RoboDK station: New Station (1).rdk

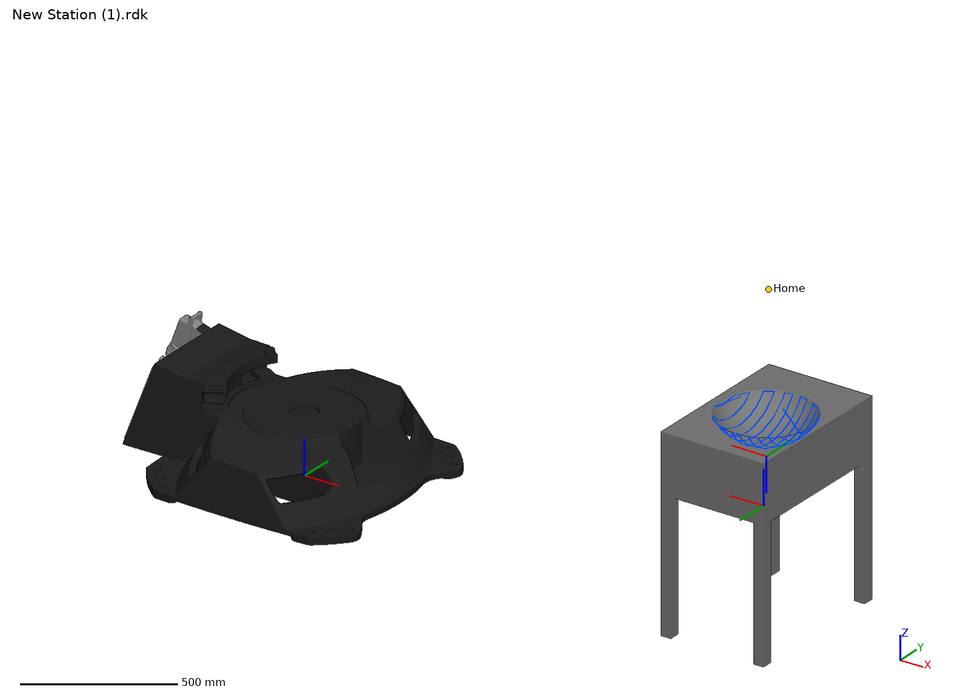
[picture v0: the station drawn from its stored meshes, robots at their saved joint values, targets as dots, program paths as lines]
Station New Station (1) (saved by RoboDK 5.5.4). Poses are relative to the parent item; angles as X-Y-Z fixed-axis rotations.
  - frame KUKA KR 90 R2700 pro Base at (0, 0, 0) mm
    - robot KUKA KR 90 R2700 pro: 6 axes, payload 90 kg, reach 2700 mm, repeatability 0.06 mm, weight 1058 kg
        joint limits [-185, -140, -120, -350, -125, -350] to [185, -5, 155, 350, 125, 350]; home [0, -90, 90, 0, 0, 0]; saved at [0, -80.946, 98.354, 0, 43.832, 0]
      - tool Nastroj, TCP at (0, 0, 70) mm, size 183.8 x 183.3 x 59.7 mm, geometry from Nastroj.stp
    - target Home (joint target) at (1800.87, 0, 1162.68) mm, rotated rx 180 ry 28.76 rz 180 deg; joints [0, -80.946, 98.354, 0, 43.832, 0] of KUKA KR 90 R2700 pro
  - frame Stul Frame at (1790, 0, 570) mm, rotated rx 180 ry 0 rz -180 deg
    - object Stul at (0, 0, 0) mm, rotated rx 0 ry 0 rz 90 deg, size 600 x 400 x 570 mm, geometry from Stul.stp
    - frame Frame Dilek_Test at (-200, -300, 0) mm, rotated rx 180 ry 0 rz 0 deg
      - object Dil23 at (0, 0, 0) mm, size 400 x 600 x 150 mm, geometry from Dil23.step
      - object Polish Path 1 at (0, 0, 0) mm, geometry from tyle
      - object Sphere at (200, -300, 250) mm, size 399.9 x 399.9 x 400 mm, geometry from Sphere.stp
  - program GoHome (3 instructions, listed below)
  - program Main (5 instructions, listed below)
  - machining project Polish Path 1 Settings: rotZ(0 | rotX(0)*rotY(0 | rotz(0) | onStart | onPathStart | onApproach | onPoint | onRetract | onFinish | SetRPM(%1) | SetTool(%1) | Extruder(%1) | default | default | OutOnMov(%1) | OutOffMov(%1) | onPathFinis | M_RunCode(%1
  - program Polish (260 instructions, listed below)
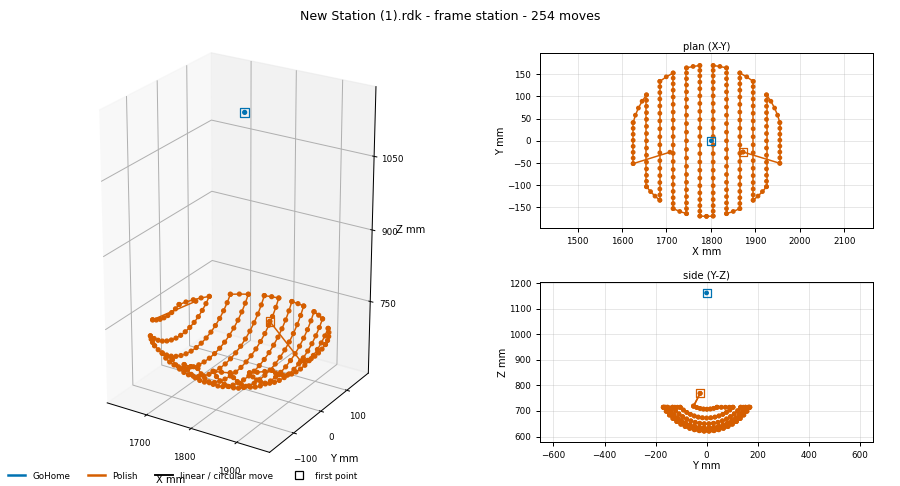
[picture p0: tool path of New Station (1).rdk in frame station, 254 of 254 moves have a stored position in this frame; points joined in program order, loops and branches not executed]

--- program GoHome (robot KUKA KR 90 R2700 pro) ---
  Set Ref.: KUKA KR 90 R2700 pro Base
  Set Tool: Nastroj
  MoveJ (Home)

--- program Main (robot KUKA KR 90 R2700 pro) ---
  Set Ref.: Stul Frame
  Set Tool: Nastroj
  Call GoHome
  Call Polish
  Call GoHome

--- program Polish (robot KUKA KR 90 R2700 pro) ---
  Smooth(1)
  Set speed (1000.0 mm/s)
  Set Ref.: Frame Dilek_Test
  Set Tool: Nastroj
  Show Nastroj
  MoveJ 1 to (117.8, -274.8, 198.93) mm, rotated rx -137.84 ry 47.58 rz 33.76 deg; joints [-1.651, -68.453, 110.438, 122.535, 19.225, -102.13]
  MoveL 2 to (117.8, -274.8, 198.93) mm, rotated rx -137.84 ry 47.58 rz 33.76 deg; joints [-1.651, -68.453, 110.438, 122.535, 19.225, -102.13]
  MoveL 3 to (35, -249.41, 148.93) mm, rotated rx -137.84 ry 47.58 rz 33.76 deg; joints [-0.725, -63.471, 106.074, 125.742, 19.006, -104.865]
  MoveL 4 to (35, -249.41, 148.93) mm, rotated rx -137.84 ry 47.58 rz 33.76 deg; joints [-0.725, -63.471, 106.074, 125.742, 19.006, -104.865]
  Set speed (50.0 mm/s)
  MoveL 5 to (35, -261.79, 143.63) mm, rotated rx -143.95 ry 51.8 rz 29.77 deg; joints [-0.584, -63.444, 106.387, 135.478, 16.911, -118.801]
  MoveL 6 to (35, -274.71, 139.84) mm, rotated rx -153.09 ry 55.89 rz 22.79 deg; joints [-0.405, -63.435, 106.629, 148.134, 15.066, -136.573]
  MoveL 7 to (35, -288, 137.61) mm, rotated rx -166 ry 58.98 rz 12.06 deg; joints [-0.198, -63.435, 106.779, 163.971, 13.789, -158.315]
  MoveL 8 to (35, -301.45, 136.98) mm, rotated rx 178.26 ry 59.98 rz -1.51 deg; joints [0.024, -63.435, 106.823, 181.974, 13.394, -182.664]
  MoveL 9 to (35, -314.88, 137.96) mm, rotated rx 162.91 ry 58.46 rz -14.69 deg; joints [0.244, -63.435, 106.756, 199.683, 13.999, -206.663]
  MoveL 10 to (35, -328.1, 140.52) mm, rotated rx 150.82 ry 55.06 rz -24.6 deg; joints [0.446, -63.436, 106.584, 214.864, 15.427, -227.6]
  MoveL 11 to (35, -340.93, 144.64) mm, rotated rx 142.41 ry 50.88 rz -30.84 deg; joints [0.618, -63.448, 106.325, 226.844, 17.35, -244.503]
  MoveL 12 to (35, -340.93, 144.64) mm, rotated rx 142.41 ry 50.88 rz -30.84 deg; joints [0.618, -63.448, 106.325, 226.844, 17.35, -244.503]
  MoveL 13 to (40.06, -357.6, 144.64) mm, rotated rx 134.65 ry 44.65 rz -35.43 deg; joints [0.868, -63.359, 106.183, 238.953, 20.907, -262.28]
  MoveL 14 to (46.79, -373.67, 144.64) mm, rotated rx 129.79 ry 38.63 rz -36.85 deg; joints [1.108, -63.241, 105.994, 248.006, 24.894, -275.71]
  MoveL 15 to (55.13, -388.96, 144.64) mm, rotated rx 126.67 ry 33.15 rz -36.29 deg; joints [1.335, -63.095, 105.759, 255.096, 29.12, -285.986]
  MoveL 16 to (65, -403.32, 144.64) mm, rotated rx 124.59 ry 28.27 rz -34.48 deg; joints [1.547, -62.923, 105.482, 260.918, 33.479, -293.97]
  MoveL 17 to (65, -403.32, 144.64) mm, rotated rx 124.59 ry 28.27 rz -34.48 deg; joints [1.547, -62.923, 105.482, 260.918, 33.479, -293.97]
  MoveL 18 to (65, -391.04, 133.86) mm, rotated rx 125.71 ry 31.05 rz -35.67 deg; joints [1.564, -62.846, 106.082, 256.775, 31.153, -288.422]
  MoveL 19 to (65, -377.64, 124.51) mm, rotated rx 127.42 ry 34.63 rz -36.6 deg; joints [1.52, -62.84, 106.709, 251.428, 28.444, -281.096]
  MoveL 20 to (65, -363.28, 116.69) mm, rotated rx 130.17 ry 39.18 rz -36.81 deg; joints [1.396, -62.894, 107.336, 244.35, 25.394, -271.155]
  MoveL 21 to (65, -348.15, 110.51) mm, rotated rx 134.83 ry 44.83 rz -35.34 deg; joints [1.177, -62.988, 107.92, 234.707, 22.143, -257.358]
  MoveL 22 to (65, -332.43, 106.05) mm, rotated rx 143.12 ry 51.31 rz -30.35 deg; joints [0.858, -63.092, 108.403, 221.278, 19.01, -238.058]
  MoveL 23 to (65, -316.32, 103.34) mm, rotated rx 157.85 ry 57.33 rz -18.91 deg; joints [0.454, -63.173, 108.726, 202.827, 16.583, -211.871]
  MoveL 24 to (65, -300, 102.44) mm, rotated rx -180 ry 60 rz 0 deg; joints [0, -63.204, 108.84, 180, 15.637, -180]
  MoveL 25 to (65, -283.68, 103.34) mm, rotated rx -157.85 ry 57.33 rz 18.91 deg; joints [-0.454, -63.173, 108.726, 157.173, 16.583, -148.129]
  MoveL 26 to (65, -267.57, 106.05) mm, rotated rx -143.12 ry 51.31 rz 30.35 deg; joints [-0.858, -63.092, 108.403, 138.722, 19.01, -121.942]
  MoveL 27 to (65, -251.85, 110.51) mm, rotated rx -134.83 ry 44.83 rz 35.34 deg; joints [-1.177, -62.988, 107.92, 125.293, 22.143, -102.642]
  MoveL 28 to (65, -236.72, 116.69) mm, rotated rx -130.17 ry 39.18 rz 36.81 deg; joints [-1.396, -62.894, 107.336, 115.65, 25.394, -88.845]
  MoveL 29 to (65, -222.36, 124.51) mm, rotated rx -127.42 ry 34.63 rz 36.6 deg; joints [-1.52, -62.84, 106.709, 108.572, 28.444, -78.904]
  MoveL 30 to (65, -208.96, 133.86) mm, rotated rx -125.71 ry 31.05 rz 35.67 deg; joints [-1.564, -62.846, 106.082, 103.225, 31.153, -71.578]
  MoveL 31 to (65, -196.68, 144.64) mm, rotated rx -124.59 ry 28.27 rz 34.48 deg; joints [-1.547, -62.923, 105.482, 99.082, 33.479, -66.03]
  MoveL 32 to (65, -196.68, 144.64) mm, rotated rx -124.59 ry 28.27 rz 34.48 deg; joints [-1.547, -62.923, 105.482, 99.082, 33.479, -66.03]
  MoveL 33 to (74.14, -185.73, 144.64) mm, rotated rx -123.39 ry 24.69 rz 32.37 deg; joints [-1.707, -62.764, 105.226, 94.954, 37.102, -60.774]
  MoveL 34 to (84.16, -175.58, 144.64) mm, rotated rx -122.49 ry 21.44 rz 29.85 deg; joints [-1.853, -62.591, 104.945, 91.234, 40.749, -56.41]
  MoveL 35 to (95, -166.3, 144.64) mm, rotated rx -121.81 ry 18.45 rz 27.04 deg; joints [-1.986, -62.403, 104.641, 87.814, 44.405, -52.76]
  MoveL 36 to (95, -166.3, 144.64) mm, rotated rx -121.81 ry 18.45 rz 27.04 deg; joints [-1.986, -62.403, 104.641, 87.814, 44.405, -52.76]
  MoveL 37 to (95, -178.23, 131.05) mm, rotated rx -122.16 ry 20.05 rz 28.61 deg; joints [-2.152, -62.223, 105.261, 90.291, 42.582, -55.761]
  MoveL 38 to (95, -191.54, 118.81) mm, rotated rx -122.68 ry 22.17 rz 30.47 deg; joints [-2.289, -62.147, 105.968, 93.437, 40.311, -59.562]
  MoveL 39 to (95, -206.07, 108.04) mm, rotated rx -123.48 ry 24.99 rz 32.57 deg; joints [-2.364, -62.183, 106.769, 97.539, 37.503, -64.587]
  MoveL 40 to (95, -221.66, 98.88) mm, rotated rx -124.8 ry 28.82 rz 34.75 deg; joints [-2.337, -62.332, 107.654, 103.058, 34.073, -71.558]
  MoveL 41 to (95, -238.13, 91.42) mm, rotated rx -127.13 ry 34.08 rz 36.5 deg; joints [-2.159, -62.577, 108.589, 110.769, 29.996, -81.74]
  MoveL 42 to (95, -255.3, 85.75) mm, rotated rx -131.69 ry 41.25 rz 36.52 deg; joints [-1.785, -62.878, 109.495, 122.04, 25.42, -97.343]
  MoveL 43 to (95, -272.98, 81.94) mm, rotated rx -141.6 ry 50.35 rz 31.4 deg; joints [-1.193, -63.162, 110.242, 139.204, 20.917, -121.85]
  MoveL 44 to (95, -290.96, 80.02) mm, rotated rx -163.62 ry 58.59 rz 14.08 deg; joints [-0.422, -63.337, 110.673, 164.721, 17.82, -158.328]
  MoveL 45 to (95, -309.04, 80.02) mm, rotated rx 163.62 ry 58.59 rz -14.08 deg; joints [0.422, -63.337, 110.673, 195.279, 17.82, -201.672]
  MoveL 46 to (95, -327.02, 81.94) mm, rotated rx 141.6 ry 50.35 rz -31.4 deg; joints [1.193, -63.162, 110.242, 220.796, 20.917, -238.15]
  MoveL 47 to (95, -344.7, 85.75) mm, rotated rx 131.69 ry 41.25 rz -36.52 deg; joints [1.785, -62.878, 109.495, 237.96, 25.42, -262.657]
  MoveL 48 to (95, -361.87, 91.42) mm, rotated rx 127.13 ry 34.08 rz -36.5 deg; joints [2.159, -62.577, 108.589, 249.231, 29.996, -278.26]
  MoveL 49 to (95, -378.34, 98.88) mm, rotated rx 124.8 ry 28.82 rz -34.75 deg; joints [2.337, -62.332, 107.654, 256.942, 34.073, -288.442]
  MoveL 50 to (95, -393.93, 108.04) mm, rotated rx 123.48 ry 24.99 rz -32.57 deg; joints [2.364, -62.183, 106.769, 262.461, 37.503, -295.413]
  MoveL 51 to (95, -408.46, 118.81) mm, rotated rx 122.68 ry 22.17 rz -30.47 deg; joints [2.289, -62.147, 105.968, 266.563, 40.311, -300.438]
  MoveL 52 to (95, -421.77, 131.05) mm, rotated rx 122.16 ry 20.05 rz -28.61 deg; joints [2.152, -62.223, 105.261, 269.709, 42.582, -304.239]
  MoveL 53 to (95, -433.7, 144.64) mm, rotated rx 121.81 ry 18.45 rz -27.04 deg; joints [1.986, -62.403, 104.641, 272.186, 44.405, -307.24]
  MoveL 54 to (95, -433.7, 144.64) mm, rotated rx 121.81 ry 18.45 rz -27.04 deg; joints [1.986, -62.403, 104.641, 272.186, 44.405, -307.24]
  MoveL 55 to (109.51, -443.91, 144.64) mm, rotated rx 121.18 ry 15.05 rz -23.23 deg; joints [2.129, -62.152, 104.236, 276.135, 48.944, -310.985]
  MoveL 56 to (125, -452.56, 144.64) mm, rotated rx 120.73 ry 11.93 rz -19.17 deg; joints [2.248, -61.886, 103.803, 279.846, 53.457, -314.032]
  MoveL 57 to (125, -452.56, 144.64) mm, rotated rx 120.73 ry 11.93 rz -19.17 deg; joints [2.248, -61.886, 103.803, 279.846, 53.457, -314.032]
  MoveL 58 to (125, -441.07, 129.7) mm, rotated rx 120.85 ry 12.85 rz -20.43 deg; joints [2.516, -61.591, 104.318, 278.333, 52.198, -312.179]
  MoveL 59 to (125, -428.13, 115.99) mm, rotated rx 121.03 ry 14.08 rz -22.02 deg; joints [2.792, -61.397, 104.923, 276.44, 50.597, -309.985]
  MoveL 60 to (125, -413.86, 103.67) mm, rotated rx 121.29 ry 15.72 rz -24.02 deg; joints [3.054, -61.324, 105.647, 273.997, 48.538, -307.265]
  MoveL 61 to (125, -398.41, 92.87) mm, rotated rx 121.71 ry 17.96 rz -26.52 deg; joints [3.266, -61.397, 106.521, 270.735, 45.86, -303.694]
  MoveL 62 to (125, -381.94, 83.68) mm, rotated rx 122.41 ry 21.12 rz -29.58 deg; joints [3.374, -61.642, 107.579, 266.195, 42.347, -298.66]
  MoveL 63 to (125, -364.63, 76.22) mm, rotated rx 123.72 ry 25.76 rz -33.07 deg; joints [3.291, -62.07, 108.833, 259.552, 37.749, -290.941]
  MoveL 64 to (125, -346.65, 70.56) mm, rotated rx 126.53 ry 32.86 rz -36.22 deg; joints [2.895, -62.656, 110.23, 249.185, 31.899, -277.935]
  MoveL 65 to (125, -328.18, 66.75) mm, rotated rx 133.86 ry 43.81 rz -35.77 deg; joints [2.055, -63.283, 111.563, 231.654, 25.165, -253.987]
  MoveL 66 to (125, -309.43, 64.83) mm, rotated rx 157.11 ry 57.13 rz -19.53 deg; joints [0.755, -63.715, 112.428, 200.767, 19.663, -209.783]
  MoveL 67 to (125, -290.57, 64.83) mm, rotated rx -157.11 ry 57.13 rz 19.53 deg; joints [-0.755, -63.715, 112.428, 159.233, 19.663, -150.217]
  MoveL 68 to (125, -271.82, 66.75) mm, rotated rx -133.86 ry 43.81 rz 35.77 deg; joints [-2.055, -63.283, 111.563, 128.346, 25.165, -106.013]
  MoveL 69 to (125, -253.35, 70.56) mm, rotated rx -126.53 ry 32.86 rz 36.22 deg; joints [-2.895, -62.656, 110.23, 110.815, 31.899, -82.065]
  MoveL 70 to (125, -235.37, 76.22) mm, rotated rx -123.72 ry 25.76 rz 33.07 deg; joints [-3.291, -62.07, 108.833, 100.448, 37.749, -69.059]
  MoveL 71 to (125, -218.06, 83.68) mm, rotated rx -122.41 ry 21.12 rz 29.58 deg; joints [-3.374, -61.642, 107.579, 93.805, 42.347, -61.34]
  MoveL 72 to (125, -201.59, 92.87) mm, rotated rx -121.71 ry 17.96 rz 26.52 deg; joints [-3.266, -61.397, 106.521, 89.265, 45.86, -56.306]
  MoveL 73 to (125, -186.14, 103.67) mm, rotated rx -121.29 ry 15.72 rz 24.02 deg; joints [-3.054, -61.324, 105.647, 86.003, 48.538, -52.735]
  MoveL 74 to (125, -171.87, 115.99) mm, rotated rx -121.03 ry 14.08 rz 22.02 deg; joints [-2.792, -61.397, 104.923, 83.56, 50.597, -50.015]
  MoveL 75 to (125, -158.93, 129.7) mm, rotated rx -120.85 ry 12.85 rz 20.43 deg; joints [-2.516, -61.591, 104.318, 81.667, 52.198, -47.821]
  MoveL 76 to (125, -147.44, 144.64) mm, rotated rx -120.73 ry 11.93 rz 19.17 deg; joints [-2.248, -61.886, 103.803, 80.154, 53.457, -45.968]
  MoveL 77 to (125, -147.44, 144.64) mm, rotated rx -120.73 ry 11.93 rz 19.17 deg; joints [-2.248, -61.886, 103.803, 80.154, 53.457, -45.968]
  MoveL 78 to (139.73, -141.04, 144.64) mm, rotated rx -120.44 ry 9.28 rz 15.35 deg; joints [-2.333, -61.633, 103.391, 76.937, 57.504, -43.692]
  MoveL 79 to (155, -136.06, 144.64) mm, rotated rx -120.23 ry 6.76 rz 11.42 deg; joints [-2.397, -61.372, 102.966, 73.808, 61.504, -41.787]
  MoveL 80 to (155, -136.06, 144.64) mm, rotated rx -120.23 ry 6.76 rz 11.42 deg; joints [-2.397, -61.372, 102.966, 73.808, 61.504, -41.787]
  MoveL 81 to (155, -147.4, 128.81) mm, rotated rx -120.27 ry 7.26 rz 12.21 deg; joints [-2.729, -60.955, 103.33, 74.64, 60.756, -43.045]
  MoveL 82 to (155, -160.25, 114.19) mm, rotated rx -120.32 ry 7.91 rz 13.25 deg; joints [-3.097, -60.617, 103.751, 75.659, 59.816, -44.421]
  MoveL 83 to (155, -174.5, 100.92) mm, rotated rx -120.39 ry 8.79 rz 14.6 deg; joints [-3.49, -60.38, 104.258, 76.96, 58.594, -45.984]
  MoveL 84 to (155, -190.01, 89.14) mm, rotated rx -120.51 ry 9.99 rz 16.41 deg; joints [-3.891, -60.275, 104.894, 78.696, 56.951, -47.857]
  MoveL 85 to (155, -206.61, 78.96) mm, rotated rx -120.7 ry 11.7 rz 18.86 deg; joints [-4.268, -60.347, 105.726, 81.135, 54.661, -50.283]
  MoveL 86 to (155, -224.14, 70.5) mm, rotated rx -121.06 ry 14.26 rz 22.24 deg; joints [-4.564, -60.659, 106.858, 84.786, 51.339, -53.778]
  MoveL 87 to (155, -242.43, 63.82) mm, rotated rx -121.79 ry 18.38 rz 26.96 deg; joints [-4.65, -61.301, 108.434, 90.708, 46.331, -59.582]
  MoveL 88 to (155, -261.3, 59.01) mm, rotated rx -123.74 ry 25.8 rz 33.1 deg; joints [-4.242, -62.359, 110.584, 101.467, 38.621, -71.244]
  MoveL 89 to (155, -280.55, 56.1) mm, rotated rx -131.44 ry 40.94 rz 36.58 deg; joints [-2.793, -63.684, 113.039, 124.666, 27.665, -100.948]
  MoveL 90 to (155, -300, 55.13) mm, rotated rx -180 ry 60 rz 0 deg; joints [0, -64.403, 114.318, 180, 19.915, -180]
  MoveL 91 to (155, -319.45, 56.1) mm, rotated rx 131.44 ry 40.94 rz -36.58 deg; joints [2.793, -63.684, 113.039, 235.334, 27.665, -259.052]
  MoveL 92 to (155, -338.7, 59.01) mm, rotated rx 123.74 ry 25.8 rz -33.1 deg; joints [4.242, -62.359, 110.584, 258.533, 38.621, -288.756]
  MoveL 93 to (155, -357.57, 63.82) mm, rotated rx 121.79 ry 18.38 rz -26.96 deg; joints [4.65, -61.301, 108.434, 269.292, 46.331, -300.418]
  MoveL 94 to (155, -375.86, 70.5) mm, rotated rx 121.06 ry 14.26 rz -22.24 deg; joints [4.564, -60.659, 106.858, 275.214, 51.339, -306.222]
  MoveL 95 to (155, -393.39, 78.96) mm, rotated rx 120.7 ry 11.7 rz -18.86 deg; joints [4.268, -60.347, 105.726, 278.865, 54.661, -309.717]
  MoveL 96 to (155, -409.99, 89.14) mm, rotated rx 120.51 ry 9.99 rz -16.41 deg; joints [3.891, -60.275, 104.894, 281.304, 56.951, -312.143]
  MoveL 97 to (155, -425.5, 100.92) mm, rotated rx 120.39 ry 8.79 rz -14.6 deg; joints [3.49, -60.38, 104.258, 283.04, 58.594, -314.016]
  MoveL 98 to (155, -439.75, 114.19) mm, rotated rx 120.32 ry 7.91 rz -13.25 deg; joints [3.097, -60.617, 103.751, 284.341, 59.816, -315.579]
  MoveL 99 to (155, -452.6, 128.81) mm, rotated rx 120.27 ry 7.26 rz -12.21 deg; joints [2.729, -60.955, 103.33, 285.36, 60.756, -316.955]
  MoveL 100 to (155, -463.94, 144.64) mm, rotated rx 120.23 ry 6.76 rz -11.42 deg; joints [2.397, -61.372, 102.966, 286.192, 61.504, -318.213]
  MoveL 101 to (155, -463.94, 144.64) mm, rotated rx 120.23 ry 6.76 rz -11.42 deg; joints [2.397, -61.372, 102.966, 286.192, 61.504, -318.213]
  MoveL 102 to (169.88, -467.31, 144.64) mm, rotated rx 120.1 ry 4.45 rz -7.63 deg; joints [2.437, -61.119, 102.551, 289.116, 65.251, -319.74]
  MoveL 103 to (185, -469.34, 144.64) mm, rotated rx 120.02 ry 2.2 rz -3.79 deg; joints [2.457, -60.862, 102.13, 292.018, 68.938, -321.036]
  MoveL 104 to (185, -469.34, 144.64) mm, rotated rx 120.02 ry 2.2 rz -3.79 deg; joints [2.457, -60.862, 102.13, 292.018, 68.938, -321.036]
  MoveL 105 to (185, -458.39, 128.8) mm, rotated rx 120.03 ry 2.35 rz -4.05 deg; joints [2.806, -60.338, 102.31, 291.766, 68.676, -320.161]
  MoveL 106 to (185, -445.96, 114.09) mm, rotated rx 120.03 ry 2.55 rz -4.4 deg; joints [3.202, -59.858, 102.491, 291.489, 68.391, -319.289]
  MoveL 107 to (185, -432.17, 100.65) mm, rotated rx 120.04 ry 2.81 rz -4.85 deg; joints [3.64, -59.435, 102.684, 291.163, 68.051, -318.412]
  MoveL 108 to (185, -417.15, 88.6) mm, rotated rx 120.05 ry 3.17 rz -5.46 deg; joints [4.117, -59.083, 102.907, 290.743, 67.612, -317.514]
  MoveL 109 to (185, -401.04, 78.05) mm, rotated rx 120.07 ry 3.68 rz -6.32 deg; joints [4.625, -58.824, 103.189, 290.153, 66.993, -316.557]
  MoveL 110 to (185, -383.99, 69.11) mm, rotated rx 120.1 ry 4.42 rz -7.57 deg; joints [5.157, -58.694, 103.584, 289.249, 66.045, -315.459]
  MoveL 111 to (185, -366.15, 61.85) mm, rotated rx 120.16 ry 5.6 rz -9.53 deg; joints [5.695, -58.759, 104.206, 287.726, 64.456, -314.033]
  MoveL 112 to (185, -347.69, 56.35) mm, rotated rx 120.3 ry 7.73 rz -12.96 deg; joints [6.191, -59.176, 105.321, 284.8, 61.459, -311.731]
  MoveL 113 to (185, -328.8, 52.65) mm, rotated rx 120.82 ry 12.61 rz -20.1 deg; joints [6.414, -60.4, 107.704, 277.746, 54.626, -306.284]
  MoveL 114 to (185, -309.63, 50.8) mm, rotated rx 126.2 ry 32.15 rz -36.02 deg; joints [4.428, -63.739, 113.538, 248.616, 34.148, -276.032]
  MoveL 115 to (185, -290.37, 50.8) mm, rotated rx -126.2 ry 32.15 rz 36.02 deg; joints [-4.428, -63.739, 113.538, 111.384, 34.148, -83.968]
  MoveL 116 to (185, -271.2, 52.65) mm, rotated rx -120.82 ry 12.61 rz 20.1 deg; joints [-6.414, -60.4, 107.704, 82.254, 54.626, -53.716]
  MoveL 117 to (185, -252.31, 56.35) mm, rotated rx -120.3 ry 7.73 rz 12.96 deg; joints [-6.191, -59.176, 105.321, 75.2, 61.459, -48.269]
  MoveL 118 to (185, -233.85, 61.85) mm, rotated rx -120.16 ry 5.6 rz 9.53 deg; joints [-5.695, -58.759, 104.206, 72.274, 64.456, -45.967]
  MoveL 119 to (185, -216.01, 69.11) mm, rotated rx -120.1 ry 4.42 rz 7.57 deg; joints [-5.157, -58.694, 103.584, 70.751, 66.045, -44.541]
  MoveL 120 to (185, -198.96, 78.05) mm, rotated rx -120.07 ry 3.68 rz 6.32 deg; joints [-4.625, -58.824, 103.189, 69.847, 66.993, -43.443]
  MoveL 121 to (185, -182.85, 88.6) mm, rotated rx -120.05 ry 3.17 rz 5.46 deg; joints [-4.117, -59.083, 102.907, 69.257, 67.612, -42.486]
  MoveL 122 to (185, -167.83, 100.65) mm, rotated rx -120.04 ry 2.81 rz 4.85 deg; joints [-3.64, -59.435, 102.684, 68.837, 68.051, -41.588]
  MoveL 123 to (185, -154.04, 114.09) mm, rotated rx -120.03 ry 2.55 rz 4.4 deg; joints [-3.202, -59.858, 102.491, 68.511, 68.391, -40.711]
  MoveL 124 to (185, -141.61, 128.8) mm, rotated rx -120.03 ry 2.35 rz 4.05 deg; joints [-2.806, -60.338, 102.31, 68.234, 68.676, -39.839]
  MoveL 125 to (185, -130.66, 144.64) mm, rotated rx -120.02 ry 2.2 rz 3.79 deg; joints [-2.457, -60.862, 102.13, 67.982, 68.938, -38.964]
  MoveL 126 to (185, -130.66, 144.64) mm, rotated rx -120.02 ry 2.2 rz 3.79 deg; joints [-2.457, -60.862, 102.13, 67.982, 68.938, -38.964]
  MoveL 127 to (200, -130, 144.64) mm, rotated rx -120 ry 0 rz 0 deg; joints [-2.457, -60.608, 101.713, 65.125, 72.498, -37.875]
  MoveL 128 to (200, -130, 144.64) mm, rotated rx -120 ry 0 rz 0 deg; joints [-2.457, -60.608, 101.713, 65.125, 72.498, -37.875]
  MoveL 129 to (215, -130.66, 144.64) mm, rotated rx -120.02 ry -2.2 rz -3.79 deg; joints [-2.439, -60.355, 101.297, 62.249, 75.98, -36.939]
  MoveL 130 to (215, -130.66, 144.64) mm, rotated rx -120.02 ry -2.2 rz -3.79 deg; joints [-2.439, -60.355, 101.297, 62.249, 75.98, -36.939]
  MoveL 131 to (215, -141.61, 128.8) mm, rotated rx -120.03 ry -2.35 rz -4.05 deg; joints [-2.78, -59.725, 101.292, 61.991, 76.147, -37.582]
  MoveL 132 to (215, -154.04, 114.09) mm, rotated rx -120.03 ry -2.55 rz -4.4 deg; joints [-3.166, -59.109, 101.231, 61.62, 76.437, -38.162]
  MoveL 133 to (215, -167.83, 100.65) mm, rotated rx -120.04 ry -2.81 rz -4.85 deg; joints [-3.589, -58.504, 101.104, 61.112, 76.877, -38.661]
  MoveL 134 to (215, -182.85, 88.6) mm, rotated rx -120.05 ry -3.17 rz -5.46 deg; joints [-4.043, -57.908, 100.893, 60.426, 77.505, -39.06]
  MoveL 135 to (215, -198.96, 78.05) mm, rotated rx -120.07 ry -3.68 rz -6.32 deg; joints [-4.517, -57.309, 100.572, 59.495, 78.392, -39.329]
  MoveL 136 to (215, -216.01, 69.11) mm, rotated rx -120.1 ry -4.42 rz -7.57 deg; joints [-4.997, -56.682, 100.086, 58.192, 79.664, -39.424]
  MoveL 137 to (215, -233.85, 61.85) mm, rotated rx -120.16 ry -5.6 rz -9.53 deg; joints [-5.45, -55.97, 99.33, 56.256, 81.585, -39.257]
  MoveL 138 to (215, -252.31, 56.35) mm, rotated rx -120.3 ry -7.73 rz -12.96 deg; joints [-5.798, -55.033, 98.045, 53.032, 84.777, -38.64]
  MoveL 139 to (215, -271.2, 52.65) mm, rotated rx -120.82 ry -12.61 rz -20.1 deg; joints [-5.747, -53.463, 95.491, 46.407, 91.036, -36.996]
  MoveL 140 to (215, -290.37, 50.8) mm, rotated rx -126.2 ry -32.15 rz -36.02 deg; joints [-3.57, -50.169, 89.663, 25.929, 105.415, -29.152]
  MoveL 141 to (215, -309.63, 50.8) mm, rotated rx 126.2 ry -32.15 rz 36.02 deg; joints [3.57, -50.169, 89.663, -25.929, 105.415, 29.152]
  MoveL 142 to (215, -328.8, 52.65) mm, rotated rx 120.82 ry -12.61 rz 20.1 deg; joints [5.747, -53.463, 95.491, -46.407, 91.036, 36.996]
  MoveL 143 to (215, -347.69, 56.35) mm, rotated rx 120.3 ry -7.73 rz 12.96 deg; joints [5.798, -55.033, 98.045, -53.032, 84.777, 38.64]
  MoveL 144 to (215, -366.15, 61.85) mm, rotated rx 120.16 ry -5.6 rz 9.53 deg; joints [5.45, -55.97, 99.33, -56.256, 81.585, 39.257]
  MoveL 145 to (215, -383.99, 69.11) mm, rotated rx 120.1 ry -4.42 rz 7.57 deg; joints [4.997, -56.682, 100.086, -58.192, 79.664, 39.424]
  MoveL 146 to (215, -401.04, 78.05) mm, rotated rx 120.07 ry -3.68 rz 6.32 deg; joints [4.517, -57.309, 100.572, -59.495, 78.392, 39.329]
  MoveL 147 to (215, -417.15, 88.6) mm, rotated rx 120.05 ry -3.17 rz 5.46 deg; joints [4.043, -57.908, 100.893, -60.426, 77.505, 39.06]
  MoveL 148 to (215, -432.17, 100.65) mm, rotated rx 120.04 ry -2.81 rz 4.85 deg; joints [3.589, -58.504, 101.104, -61.112, 76.877, 38.661]
  MoveL 149 to (215, -445.96, 114.09) mm, rotated rx 120.03 ry -2.55 rz 4.4 deg; joints [3.166, -59.109, 101.231, -61.62, 76.437, 38.162]
  MoveL 150 to (215, -458.39, 128.8) mm, rotated rx 120.03 ry -2.35 rz 4.05 deg; joints [2.78, -59.725, 101.292, -61.991, 76.147, 37.582]
  MoveL 151 to (215, -469.34, 144.64) mm, rotated rx 120.02 ry -2.2 rz 3.79 deg; joints [2.439, -60.355, 101.297, -62.249, 75.98, 36.939]
  MoveL 152 to (215, -469.34, 144.64) mm, rotated rx 120.02 ry -2.2 rz 3.79 deg; joints [2.439, -60.355, 101.297, -62.249, 75.98, 36.939]
  MoveL 153 to (230.12, -467.31, 144.64) mm, rotated rx 120.1 ry -4.45 rz 7.63 deg; joints [2.4, -60.1, 100.877, -59.287, 79.43, 36.113]
  MoveL 154 to (245, -463.94, 144.64) mm, rotated rx 120.23 ry -6.76 rz 11.42 deg; joints [2.343, -59.85, 100.464, -56.269, 82.78, 35.384]
  MoveL 155 to (245, -463.94, 144.64) mm, rotated rx 120.23 ry -6.76 rz 11.42 deg; joints [2.343, -59.85, 100.464, -56.269, 82.78, 35.384]
  MoveL 156 to (245, -452.6, 128.81) mm, rotated rx 120.27 ry -7.26 rz 12.21 deg; joints [2.654, -59.117, 100.276, -55.485, 83.345, 35.86]
  MoveL 157 to (245, -439.75, 114.19) mm, rotated rx 120.32 ry -7.91 rz 13.25 deg; joints [2.993, -58.37, 99.977, -54.446, 84.167, 36.232]
  MoveL 158 to (245, -425.5, 100.92) mm, rotated rx 120.39 ry -8.79 rz 14.6 deg; joints [3.344, -57.598, 99.539, -53.077, 85.311, 36.471]
  MoveL 159 to (245, -409.99, 89.14) mm, rotated rx 120.51 ry -9.99 rz 16.41 deg; joints [3.686, -56.786, 98.923, -51.257, 86.872, 36.538]
  MoveL 160 to (245, -393.39, 78.96) mm, rotated rx 120.7 ry -11.7 rz 18.86 deg; joints [3.983, -55.906, 98.068, -48.79, 88.999, 36.37]
  MoveL 161 to (245, -375.86, 70.5) mm, rotated rx 121.06 ry -14.26 rz 22.24 deg; joints [4.17, -54.909, 96.878, -45.327, 91.922, 35.853]
  MoveL 162 to (245, -357.57, 63.82) mm, rotated rx 121.79 ry -18.38 rz 26.96 deg; joints [4.127, -53.729, 95.228, -40.213, 95.964, 34.709]
  MoveL 163 to (245, -338.7, 59.01) mm, rotated rx 123.74 ry -25.8 rz 33.1 deg; joints [3.62, -52.317, 93.018, -32.182, 101.407, 32.035]
  MoveL 164 to (245, -319.45, 56.1) mm, rotated rx 131.44 ry -40.94 rz 36.58 deg; joints [2.279, -50.846, 90.552, -19.084, 107.589, 23.952]
  MoveL 165 to (245, -300, 55.13) mm, rotated rx -180 ry -60 rz 0 deg; joints [0, -50.115, 89.289, 0, 110.826, 0]
  MoveL 166 to (245, -280.55, 56.1) mm, rotated rx -131.44 ry -40.94 rz -36.58 deg; joints [-2.279, -50.846, 90.552, 19.084, 107.589, -23.952]
  MoveL 167 to (245, -261.3, 59.01) mm, rotated rx -123.74 ry -25.8 rz -33.1 deg; joints [-3.62, -52.317, 93.018, 32.182, 101.407, -32.035]
  MoveL 168 to (245, -242.43, 63.82) mm, rotated rx -121.79 ry -18.38 rz -26.96 deg; joints [-4.127, -53.729, 95.228, 40.213, 95.964, -34.709]
  MoveL 169 to (245, -224.14, 70.5) mm, rotated rx -121.06 ry -14.26 rz -22.24 deg; joints [-4.17, -54.909, 96.878, 45.327, 91.922, -35.853]
  MoveL 170 to (245, -206.61, 78.96) mm, rotated rx -120.7 ry -11.7 rz -18.86 deg; joints [-3.983, -55.906, 98.068, 48.79, 88.999, -36.37]
  MoveL 171 to (245, -190.01, 89.14) mm, rotated rx -120.51 ry -9.99 rz -16.41 deg; joints [-3.686, -56.786, 98.923, 51.257, 86.872, -36.538]
  MoveL 172 to (245, -174.5, 100.92) mm, rotated rx -120.39 ry -8.79 rz -14.6 deg; joints [-3.344, -57.598, 99.539, 53.077, 85.311, -36.471]
  MoveL 173 to (245, -160.25, 114.19) mm, rotated rx -120.32 ry -7.91 rz -13.25 deg; joints [-2.993, -58.37, 99.977, 54.446, 84.167, -36.232]
  MoveL 174 to (245, -147.4, 128.81) mm, rotated rx -120.27 ry -7.26 rz -12.21 deg; joints [-2.654, -59.117, 100.276, 55.485, 83.345, -35.86]
  MoveL 175 to (245, -136.06, 144.64) mm, rotated rx -120.23 ry -6.76 rz -11.42 deg; joints [-2.343, -59.85, 100.464, 56.269, 82.78, -35.384]
  MoveL 176 to (245, -136.06, 144.64) mm, rotated rx -120.23 ry -6.76 rz -11.42 deg; joints [-2.343, -59.85, 100.464, 56.269, 82.78, -35.384]
  MoveL 177 to (260.27, -141.04, 144.64) mm, rotated rx -120.44 ry -9.28 rz -15.35 deg; joints [-2.263, -59.594, 100.041, 53.015, 86.183, -34.684]
  MoveL 178 to (275, -147.44, 144.64) mm, rotated rx -120.73 ry -11.93 rz -19.17 deg; joints [-2.165, -59.348, 99.633, 49.662, 89.447, -34.014]
  MoveL 179 to (275, -147.44, 144.64) mm, rotated rx -120.73 ry -11.93 rz -19.17 deg; joints [-2.165, -59.348, 99.633, 49.662, 89.447, -34.014]
  MoveL 180 to (275, -158.93, 129.7) mm, rotated rx -120.85 ry -12.85 rz -20.43 deg; joints [-2.404, -58.562, 99.288, 48.328, 90.338, -34.296]
  MoveL 181 to (275, -171.87, 115.99) mm, rotated rx -121.03 ry -14.08 rz -22.02 deg; joints [-2.642, -57.748, 98.804, 46.611, 91.554, -34.433]
  MoveL 182 to (275, -186.14, 103.67) mm, rotated rx -121.29 ry -15.72 rz -24.02 deg; joints [-2.854, -56.899, 98.158, 44.4, 93.154, -34.374]
  MoveL 183 to (275, -201.59, 92.87) mm, rotated rx -121.71 ry -17.96 rz -26.52 deg; joints [-3.005, -56.005, 97.323, 41.533, 95.205, -34.038]
  MoveL 184 to (275, -218.06, 83.68) mm, rotated rx -122.41 ry -21.12 rz -29.58 deg; joints [-3.046, -55.059, 96.275, 37.77, 97.777, -33.267]
  MoveL 185 to (275, -235.37, 76.22) mm, rotated rx -123.72 ry -25.76 rz -33.07 deg; joints [-2.904, -54.064, 95.011, 32.758, 100.886, -31.716]
  MoveL 186 to (275, -253.35, 70.56) mm, rotated rx -126.53 ry -32.86 rz -36.22 deg; joints [-2.49, -53.062, 93.601, 26.024, 104.387, -28.558]
  MoveL 187 to (275, -271.82, 66.75) mm, rotated rx -133.86 ry -43.81 rz -35.77 deg; joints [-1.726, -52.174, 92.261, 17.102, 107.757, -21.867]
  MoveL 188 to (275, -290.57, 64.83) mm, rotated rx -157.11 ry -57.13 rz -19.53 deg; joints [-0.624, -51.624, 91.398, 6.023, 109.962, -8.767]
  MoveL 189 to (275, -309.43, 64.83) mm, rotated rx 157.11 ry -57.13 rz 19.53 deg; joints [0.624, -51.624, 91.398, -6.023, 109.962, 8.767]
  MoveL 190 to (275, -328.18, 66.75) mm, rotated rx 133.86 ry -43.81 rz 35.77 deg; joints [1.726, -52.174, 92.261, -17.102, 107.757, 21.867]
  MoveL 191 to (275, -346.65, 70.56) mm, rotated rx 126.53 ry -32.86 rz 36.22 deg; joints [2.49, -53.062, 93.601, -26.024, 104.387, 28.558]
  MoveL 192 to (275, -364.63, 76.22) mm, rotated rx 123.72 ry -25.76 rz 33.07 deg; joints [2.904, -54.064, 95.011, -32.758, 100.886, 31.716]
  MoveL 193 to (275, -381.94, 83.68) mm, rotated rx 122.41 ry -21.12 rz 29.58 deg; joints [3.046, -55.059, 96.275, -37.77, 97.777, 33.267]
  MoveL 194 to (275, -398.41, 92.87) mm, rotated rx 121.71 ry -17.96 rz 26.52 deg; joints [3.005, -56.005, 97.323, -41.533, 95.205, 34.038]
  MoveL 195 to (275, -413.86, 103.67) mm, rotated rx 121.29 ry -15.72 rz 24.02 deg; joints [2.854, -56.899, 98.158, -44.4, 93.154, 34.374]
  MoveL 196 to (275, -428.13, 115.99) mm, rotated rx 121.03 ry -14.08 rz 22.02 deg; joints [2.642, -57.748, 98.804, -46.611, 91.554, 34.433]
  MoveL 197 to (275, -441.07, 129.7) mm, rotated rx 120.85 ry -12.85 rz 20.43 deg; joints [2.404, -58.562, 99.288, -48.328, 90.338, 34.296]
  MoveL 198 to (275, -452.56, 144.64) mm, rotated rx 120.73 ry -11.93 rz 19.17 deg; joints [2.165, -59.348, 99.633, -49.662, 89.447, 34.014]
  MoveL 199 to (275, -452.56, 144.64) mm, rotated rx 120.73 ry -11.93 rz 19.17 deg; joints [2.165, -59.348, 99.633, -49.662, 89.447, 34.014]
  MoveL 200 to (290.49, -443.91, 144.64) mm, rotated rx 121.18 ry -15.05 rz 23.23 deg; joints [2.034, -59.09, 99.204, -45.824, 92.87, 33.249]
  MoveL 201 to (305, -433.7, 144.64) mm, rotated rx 121.81 ry -18.45 rz 27.04 deg; joints [1.883, -58.849, 98.803, -41.828, 96.078, 32.383]
  MoveL 202 to (305, -433.7, 144.64) mm, rotated rx 121.81 ry -18.45 rz 27.04 deg; joints [1.883, -58.849, 98.803, -41.828, 96.078, 32.383]
  MoveL 203 to (305, -421.77, 131.05) mm, rotated rx 122.16 ry -20.05 rz 28.61 deg; joints [2.021, -58.053, 98.343, -39.834, 97.206, 32.33]
  MoveL 204 to (305, -408.46, 118.81) mm, rotated rx 122.68 ry -22.17 rz 30.47 deg; joints [2.124, -57.238, 97.754, -37.326, 98.646, 32.012]
  MoveL 205 to (305, -393.93, 108.04) mm, rotated rx 123.48 ry -24.99 rz 32.57 deg; joints [2.164, -56.412, 97.037, -34.184, 100.4, 31.3]
  MoveL 206 to (305, -378.34, 98.88) mm, rotated rx 124.8 ry -28.82 rz 34.75 deg; joints [2.107, -55.587, 96.206, -30.256, 102.442, 29.965]
  MoveL 207 to (305, -361.87, 91.42) mm, rotated rx 127.13 ry -34.08 rz 36.5 deg; joints [1.914, -54.792, 95.305, -25.369, 104.673, 27.59]
  MoveL 208 to (305, -344.7, 85.75) mm, rotated rx 131.69 ry -41.25 rz 36.52 deg; joints [1.557, -54.078, 94.418, -19.374, 106.888, 23.435]
  MoveL 209 to (305, -327.02, 81.94) mm, rotated rx 141.6 ry -50.35 rz 31.4 deg; joints [1.027, -53.522, 93.683, -12.241, 108.745, 16.452]
  MoveL 210 to (305, -309.04, 80.02) mm, rotated rx 163.62 ry -58.59 rz 14.08 deg; joints [0.36, -53.212, 93.258, -4.199, 109.826, 6.061]
  MoveL 211 to (305, -290.96, 80.02) mm, rotated rx -163.62 ry -58.59 rz -14.08 deg; joints [-0.36, -53.212, 93.258, 4.199, 109.826, -6.061]
  MoveL 212 to (305, -272.98, 81.94) mm, rotated rx -141.6 ry -50.35 rz -31.4 deg; joints [-1.027, -53.522, 93.683, 12.241, 108.745, -16.452]
  MoveL 213 to (305, -255.3, 85.75) mm, rotated rx -131.69 ry -41.25 rz -36.52 deg; joints [-1.557, -54.078, 94.418, 19.374, 106.888, -23.435]
  MoveL 214 to (305, -238.13, 91.42) mm, rotated rx -127.13 ry -34.08 rz -36.5 deg; joints [-1.914, -54.792, 95.305, 25.369, 104.673, -27.59]
  MoveL 215 to (305, -221.66, 98.88) mm, rotated rx -124.8 ry -28.82 rz -34.75 deg; joints [-2.107, -55.587, 96.206, 30.256, 102.442, -29.965]
  MoveL 216 to (305, -206.07, 108.04) mm, rotated rx -123.48 ry -24.99 rz -32.57 deg; joints [-2.164, -56.412, 97.037, 34.184, 100.4, -31.3]
  MoveL 217 to (305, -191.54, 118.81) mm, rotated rx -122.68 ry -22.17 rz -30.47 deg; joints [-2.124, -57.238, 97.754, 37.326, 98.646, -32.012]
  MoveL 218 to (305, -178.23, 131.05) mm, rotated rx -122.16 ry -20.05 rz -28.61 deg; joints [-2.021, -58.053, 98.343, 39.834, 97.206, -32.33]
  MoveL 219 to (305, -166.3, 144.64) mm, rotated rx -121.81 ry -18.45 rz -27.04 deg; joints [-1.883, -58.849, 98.803, 41.828, 96.078, -32.383]
  MoveL 220 to (305, -166.3, 144.64) mm, rotated rx -121.81 ry -18.45 rz -27.04 deg; joints [-1.883, -58.849, 98.803, 41.828, 96.078, -32.383]
  MoveL 221 to (315.84, -175.58, 144.64) mm, rotated rx -122.49 ry -21.44 rz -29.85 deg; joints [-1.748, -58.669, 98.503, 38.489, 98.482, -31.544]
  MoveL 222 to (325.86, -185.73, 144.64) mm, rotated rx -123.39 ry -24.69 rz -32.37 deg; joints [-1.602, -58.503, 98.226, 35.03, 100.716, -30.508]
  MoveL 223 to (335, -196.68, 144.64) mm, rotated rx -124.59 ry -28.27 rz -34.48 deg; joints [-1.445, -58.352, 97.973, 31.448, 102.764, -29.195]
  MoveL 224 to (335, -196.68, 144.64) mm, rotated rx -124.59 ry -28.27 rz -34.48 deg; joints [-1.445, -58.352, 97.973, 31.448, 102.764, -29.195]
  MoveL 225 to (335, -208.96, 133.86) mm, rotated rx -125.71 ry -31.05 rz -35.67 deg; joints [-1.447, -57.663, 97.506, 28.683, 103.897, -28.26]
  MoveL 226 to (335, -222.36, 124.51) mm, rotated rx -127.42 ry -34.63 rz -36.6 deg; joints [-1.392, -56.999, 96.98, 25.361, 105.18, -26.725]
  MoveL 227 to (335, -236.72, 116.69) mm, rotated rx -130.17 ry -39.18 rz -36.81 deg; joints [-1.265, -56.383, 96.429, 21.425, 106.538, -24.315]
  MoveL 228 to (335, -251.85, 110.51) mm, rotated rx -134.83 ry -44.83 rz -35.34 deg; joints [-1.055, -55.844, 95.899, 16.848, 107.853, -20.661]
  MoveL 229 to (335, -267.57, 106.05) mm, rotated rx -143.12 ry -51.31 rz -30.35 deg; joints [-0.763, -55.418, 95.451, 11.658, 108.974, -15.374]
  MoveL 230 to (335, -283.68, 103.34) mm, rotated rx -157.85 ry -57.33 rz -18.91 deg; joints [-0.401, -55.143, 95.149, 5.97, 109.736, -8.312]
  MoveL 231 to (335, -300, 102.44) mm, rotated rx -180 ry -60 rz 0 deg; joints [0, -55.048, 95.041, 0, 110.007, 0]
  MoveL 232 to (335, -316.32, 103.34) mm, rotated rx 157.85 ry -57.33 rz 18.91 deg; joints [0.401, -55.143, 95.149, -5.97, 109.736, 8.312]
  MoveL 233 to (335, -332.43, 106.05) mm, rotated rx 143.12 ry -51.31 rz 30.35 deg; joints [0.763, -55.418, 95.451, -11.658, 108.974, 15.374]
  MoveL 234 to (335, -348.15, 110.51) mm, rotated rx 134.83 ry -44.83 rz 35.34 deg; joints [1.055, -55.844, 95.899, -16.848, 107.853, 20.661]
  MoveL 235 to (335, -363.28, 116.69) mm, rotated rx 130.17 ry -39.18 rz 36.81 deg; joints [1.265, -56.383, 96.429, -21.425, 106.538, 24.315]
  MoveL 236 to (335, -377.64, 124.51) mm, rotated rx 127.42 ry -34.63 rz 36.6 deg; joints [1.392, -56.999, 96.98, -25.361, 105.18, 26.725]
  MoveL 237 to (335, -391.04, 133.86) mm, rotated rx 125.71 ry -31.05 rz 35.67 deg; joints [1.447, -57.663, 97.506, -28.683, 103.897, 28.26]
  MoveL 238 to (335, -403.32, 144.64) mm, rotated rx 124.59 ry -28.27 rz 34.48 deg; joints [1.445, -58.352, 97.973, -31.448, 102.764, 29.195]
  MoveL 239 to (335, -403.32, 144.64) mm, rotated rx 124.59 ry -28.27 rz 34.48 deg; joints [1.445, -58.352, 97.973, -31.448, 102.764, 29.195]
  MoveL 240 to (344.87, -388.96, 144.64) mm, rotated rx 126.67 ry -33.15 rz 36.29 deg; joints [1.241, -58.189, 97.701, -26.904, 104.991, 27.075]
  MoveL 241 to (353.21, -373.67, 144.64) mm, rotated rx 129.79 ry -38.63 rz 36.85 deg; joints [1.026, -58.051, 97.47, -22.181, 106.891, 24.2]
  MoveL 242 to (359.94, -357.6, 144.64) mm, rotated rx 134.65 ry -44.65 rz 35.43 deg; joints [0.801, -57.94, 97.284, -17.294, 108.436, 20.369]
  MoveL 243 to (365, -340.93, 144.64) mm, rotated rx 142.41 ry -50.88 rz 30.84 deg; joints [0.568, -57.857, 97.145, -12.267, 109.605, 15.439]
  MoveL 244 to (365, -340.93, 144.64) mm, rotated rx 142.41 ry -50.88 rz 30.84 deg; joints [0.568, -57.857, 97.145, -12.267, 109.605, 15.439]
  MoveL 245 to (365, -327.99, 140.49) mm, rotated rx 150.91 ry -55.1 rz 24.53 deg; joints [0.408, -57.577, 96.938, -8.497, 110.111, 11.159]
  MoveL 246 to (365, -314.64, 137.93) mm, rotated rx 163.16 ry -58.51 rz 14.47 deg; joints [0.22, -57.398, 96.799, -4.484, 110.452, 6.066]
  MoveL 247 to (365, -301.09, 136.98) mm, rotated rx 178.69 ry -59.99 rz 1.13 deg; joints [0.017, -57.331, 96.745, -0.335, 110.584, 0.458]
  MoveL 248 to (365, -287.52, 137.66) mm, rotated rx -165.47 ry -58.9 rz -12.51 deg; joints [-0.188, -57.379, 96.784, 3.825, 110.489, -5.191]
  MoveL 249 to (365, -274.13, 139.97) mm, rotated rx -152.6 ry -55.73 rz -23.18 deg; joints [-0.379, -57.541, 96.91, 7.868, 110.178, -10.392]
  MoveL 250 to (365, -261.11, 143.87) mm, rotated rx -143.55 ry -51.57 rz -30.05 deg; joints [-0.545, -57.806, 97.108, 11.683, 109.695, -14.814]
  MoveL 251 to (365, -248.66, 149.31) mm, rotated rx -137.54 ry -47.33 rz -33.94 deg; joints [-0.677, -58.158, 97.353, 15.185, 109.098, -18.339]
  Set speed (1000.0 mm/s)
  MoveL 252 to (365, -248.66, 149.31) mm, rotated rx -137.54 ry -47.33 rz -33.94 deg; joints [-0.677, -58.158, 97.353, 15.185, 109.098, -18.339]
  MoveL 253 to (282.31, -274.39, 199.31) mm, rotated rx -137.54 ry -47.33 rz -33.94 deg; joints [-1.407, -56.501, 91.519, 14.948, 113.283, -17.777]
